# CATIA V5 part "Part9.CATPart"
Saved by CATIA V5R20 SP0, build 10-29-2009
Part number: 9FP1205M4
Revision: ANY
Definition: UNKNOWN
Nomenclature: 9FP1205M4
Source: Unknown
Bounding box of the stored display mesh (mm): x -5.752 to 5.752, y 0 to 5, z -5.9 to 5.9
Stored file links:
  C:\Users\Utente\Desktop\IO LAVORO\3D X SITO CF\CUMSA\3D files PW\pw060830\pw060830_injection\Part9.CATPart
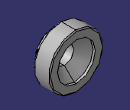
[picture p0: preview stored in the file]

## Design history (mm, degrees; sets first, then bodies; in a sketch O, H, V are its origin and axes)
Body1 "Redondeo2" (main body)
  Solid1: solid without history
